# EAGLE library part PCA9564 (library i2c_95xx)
Parallel Bus to I²C Bus Controller
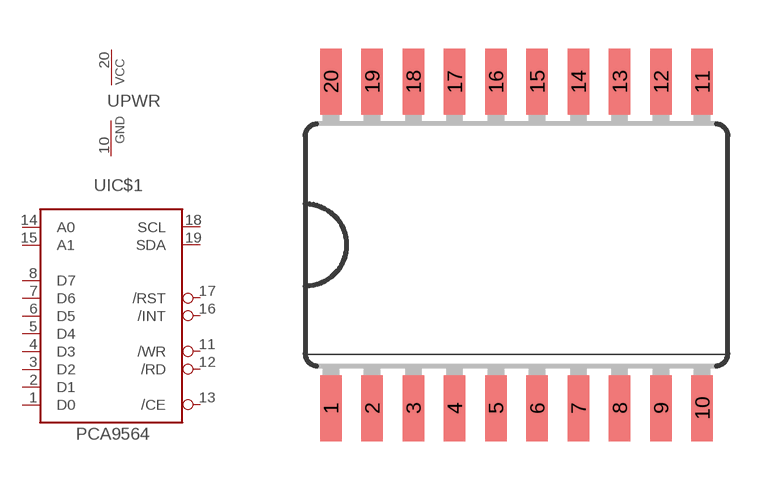
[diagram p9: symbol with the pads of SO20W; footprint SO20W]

Designator prefix -; gates PWR=PWRN IC$1=PCA9564

## PCA9564D  [SO20W]
1  IC$1:D0
2  IC$1:D1
3  IC$1:D2
4  IC$1:D3
5  IC$1:D4
6  IC$1:D5
7  IC$1:D6
8  IC$1:D7
10  PWR:GND  pwr
11  IC$1:/WR  in
12  IC$1:/RD  in
13  IC$1:/CE  in
14  IC$1:A0  in
15  IC$1:A1  in
16  IC$1:/INT  out
17  IC$1:/RST  in
18  IC$1:SCL
19  IC$1:SDA
20  PWR:VCC  pwr

## Footprint SO20W (pad centres in mm)
smd 0.66 x 2.032: 1 -5.715,-5.029; 2 -4.445,-5.029; 3 -3.175,-5.029; 4 -1.905,-5.029; 5 -0.635,-5.029; 6 0.635,-5.029; 7 1.905,-5.029; 8 3.175,-5.029; 9 4.445,-5.029; 10 5.715,-5.029; 11 5.715,5.029; 12 4.445,5.029; 13 3.175,5.029; 14 1.905,5.029; 15 0.635,5.029; 16 -0.635,5.029; 17 -1.905,5.029; 18 -3.175,5.029; 19 -4.445,5.029; 20 -5.715,5.029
